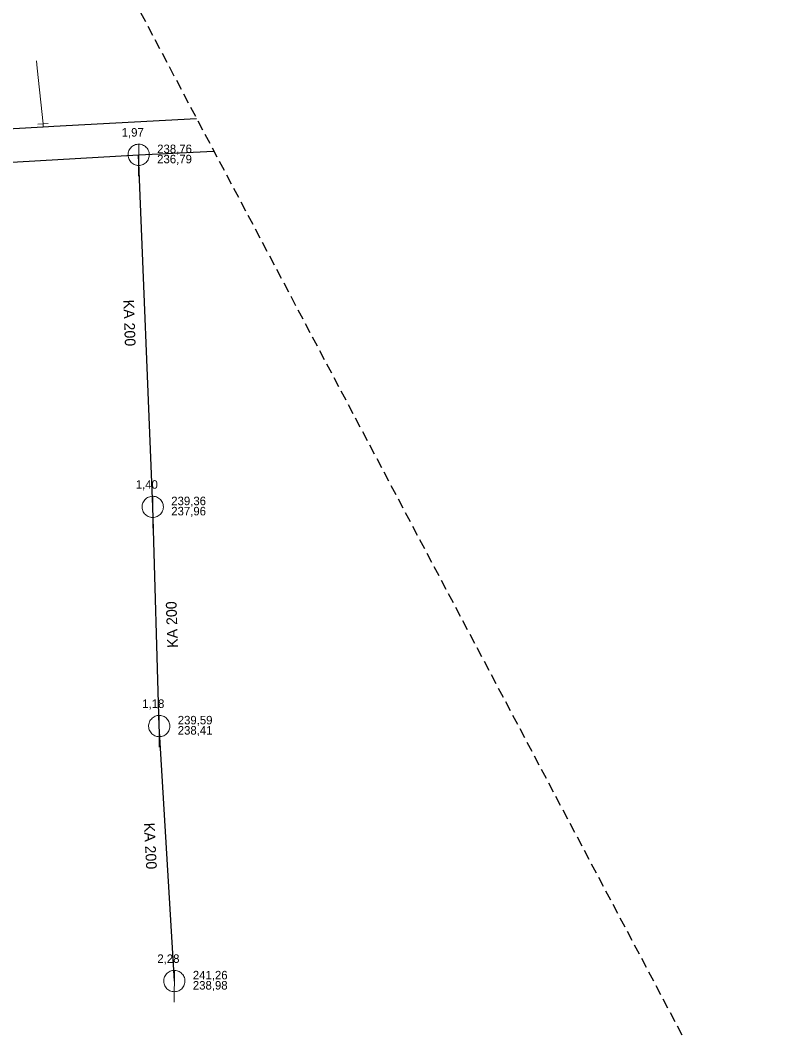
# Model space of a CAD drawing. Extents: x -777996 to -777727, y -976581 to -976199.
# Drawn here: x -777798.1 to -777726.8, y -976473.6 to -976378.6 of the extents above; entities that cross this region are included whole.
import ezdxf

# ---------------------------------------------------------------- set-up
doc = ezdxf.new("R2010")
doc.units = 0
doc.header["$LTSCALE"] = 0.32
doc.linetypes.add('MEDIUM_DASHED', pattern=[4.5, 3, -1.5])
for name, color, linetype, lineweight in [('1', 7, 'MEDIUM_DASHED', 25), ('13', 7, 'Continuous', 13), ('14', 7, 'Continuous', 25), ('17', 7, 'Continuous', 25), ('22', 7, 'Continuous', 13), ('34', 7, 'Continuous', 13)]:
    doc.layers.add(name, color=color, linetype=linetype, lineweight=lineweight)

msp = doc.modelspace()

# ---------------------------------------------------------------- linework, layer by layer
at = {"layer": '1'}
msp.add_lwpolyline([(-777995.417, -976203.033), (-777848.18, -976198.846), (-777864.927, -976230.247), (-777726.762, -976491.225), (-777789.565, -976581.242), (-777941.686, -976558.215), (-777989.136, -976405.396)], close=True, dxfattribs=at)
at = {"layer": '13'}
msp.add_lwpolyline([(-777795.959, -976388.351), (-777796.511, -976383.099), (-777796.57, -976382.41)], dxfattribs=at)
at = {"layer": '14', "lineweight": 13}
msp.add_line((-777795.936, -976388.625), (-777795.959, -976388.351), dxfattribs=at)
at = {"layer": '14'}
for p, q in [((-777785.625, -976424.436), (-777786.952, -976391.269)), ((-777785.013, -976445.085), (-777785.625, -976424.436)), ((-777783.592, -976469.103), (-777785.013, -976445.085))]:
    msp.add_line(p, q, dxfattribs=at)
msp.add_lwpolyline([(-777815.219, -976392.916), (-777786.952, -976391.269), (-777779.87, -976390.911)], dxfattribs=at)
at = {"layer": '17'}
msp.add_lwpolyline([(-777835.751, -976390.694), (-777818.616, -976389.892), (-777817.883, -976389.866), (-777816.903, -976389.831), (-777811.028, -976389.493), (-777795.936, -976388.625), (-777794.949, -976388.572), (-777781.49, -976387.851)], dxfattribs=at)
at = {"layer": '22'}
for p, q in [((-777786.952, -976393.269), (-777786.951, -976390.269)), ((-777785.625, -976426.436), (-777785.624, -976423.436)), ((-777785.014, -976447.085), (-777785.013, -976444.085)), ((-777783.593, -976471.103), (-777783.592, -976468.103))]:
    msp.add_line(p, q, dxfattribs=at)
for points in [[(-777785.952, -976391.269), (-777785.957, -976391.16), (-777785.975, -976391.052), (-777786.005, -976390.946), (-777786.045, -976390.845), (-777786.097, -976390.748), (-777786.159, -976390.658), (-777786.231, -976390.575), (-777786.311, -976390.501), (-777786.399, -976390.435), (-777786.493, -976390.38), (-777786.593, -976390.335), (-777786.698, -976390.302), (-777786.805, -976390.28), (-777786.914, -976390.27), (-777787.024, -976390.272), (-777787.132, -976390.286), (-777787.239, -976390.311), (-777787.342, -976390.348), (-777787.44, -976390.397), (-777787.532, -976390.455), (-777787.618, -976390.524), (-777787.695, -976390.601), (-777787.764, -976390.687), (-777787.823, -976390.779), (-777787.871, -976390.877), (-777787.908, -976390.98), (-777787.934, -976391.087), (-777787.948, -976391.195), (-777787.951, -976391.305), (-777787.941, -976391.414), (-777787.92, -976391.521), (-777787.886, -976391.625), (-777787.842, -976391.725), (-777787.787, -976391.82), (-777787.721, -976391.908), (-777787.647, -976391.988), (-777787.564, -976392.06), (-777787.474, -976392.122), (-777787.378, -976392.174), (-777787.276, -976392.215), (-777787.171, -976392.245), (-777787.063, -976392.263), (-777786.953, -976392.269), (-777786.844, -976392.263), (-777786.736, -976392.245), (-777786.631, -976392.216), (-777786.529, -976392.175), (-777786.432, -976392.123), (-777786.342, -976392.061), (-777786.259, -976391.99), (-777786.184, -976391.91), (-777786.119, -976391.822), (-777786.063, -976391.728), (-777786.019, -976391.628), (-777785.985, -976391.524), (-777785.963, -976391.416), (-777785.953, -976391.307)], [(-777784.625, -976424.436), (-777784.63, -976424.327), (-777784.648, -976424.219), (-777784.678, -976424.113), (-777784.718, -976424.012), (-777784.77, -976423.915), (-777784.832, -976423.825), (-777784.904, -976423.742), (-777784.984, -976423.668), (-777785.072, -976423.602), (-777785.166, -976423.547), (-777785.266, -976423.502), (-777785.371, -976423.469), (-777785.478, -976423.447), (-777785.587, -976423.437), (-777785.697, -976423.439), (-777785.805, -976423.453), (-777785.912, -976423.478), (-777786.015, -976423.515), (-777786.113, -976423.564), (-777786.205, -976423.622), (-777786.291, -976423.691), (-777786.368, -976423.768), (-777786.437, -976423.854), (-777786.496, -976423.946), (-777786.544, -976424.044), (-777786.581, -976424.147), (-777786.607, -976424.254), (-777786.621, -976424.362), (-777786.624, -976424.472), (-777786.614, -976424.581), (-777786.593, -976424.688), (-777786.559, -976424.792), (-777786.515, -976424.892), (-777786.46, -976424.987), (-777786.394, -976425.075), (-777786.32, -976425.155), (-777786.237, -976425.227), (-777786.147, -976425.289), (-777786.051, -976425.341), (-777785.949, -976425.382), (-777785.844, -976425.412), (-777785.736, -976425.43), (-777785.626, -976425.436), (-777785.517, -976425.43), (-777785.409, -976425.412), (-777785.304, -976425.383), (-777785.202, -976425.342), (-777785.105, -976425.29), (-777785.015, -976425.228), (-777784.932, -976425.157), (-777784.857, -976425.077), (-777784.792, -976424.989), (-777784.736, -976424.895), (-777784.692, -976424.795), (-777784.658, -976424.691), (-777784.636, -976424.583), (-777784.626, -976424.474)], [(-777784.014, -976445.085), (-777784.019, -976444.976), (-777784.037, -976444.868), (-777784.067, -976444.762), (-777784.107, -976444.661), (-777784.159, -976444.564), (-777784.221, -976444.474), (-777784.293, -976444.391), (-777784.373, -976444.317), (-777784.461, -976444.251), (-777784.555, -976444.196), (-777784.655, -976444.151), (-777784.76, -976444.118), (-777784.867, -976444.096), (-777784.976, -976444.086), (-777785.086, -976444.088), (-777785.194, -976444.102), (-777785.301, -976444.127), (-777785.404, -976444.164), (-777785.502, -976444.213), (-777785.594, -976444.271), (-777785.68, -976444.34), (-777785.757, -976444.417), (-777785.826, -976444.503), (-777785.885, -976444.595), (-777785.933, -976444.693), (-777785.97, -976444.796), (-777785.996, -976444.903), (-777786.01, -976445.011), (-777786.013, -976445.121), (-777786.003, -976445.23), (-777785.982, -976445.337), (-777785.948, -976445.441), (-777785.904, -976445.541), (-777785.849, -976445.636), (-777785.783, -976445.724), (-777785.709, -976445.804), (-777785.626, -976445.876), (-777785.536, -976445.938), (-777785.44, -976445.99), (-777785.338, -976446.031), (-777785.233, -976446.061), (-777785.125, -976446.079), (-777785.015, -976446.085), (-777784.906, -976446.079), (-777784.798, -976446.061), (-777784.693, -976446.032), (-777784.591, -976445.991), (-777784.494, -976445.939), (-777784.404, -976445.877), (-777784.321, -976445.806), (-777784.246, -976445.726), (-777784.181, -976445.638), (-777784.125, -976445.544), (-777784.081, -976445.444), (-777784.047, -976445.34), (-777784.025, -976445.232), (-777784.015, -976445.123)], [(-777782.593, -976469.103), (-777782.598, -976468.994), (-777782.616, -976468.886), (-777782.646, -976468.78), (-777782.686, -976468.679), (-777782.738, -976468.582), (-777782.8, -976468.492), (-777782.872, -976468.409), (-777782.952, -976468.335), (-777783.04, -976468.269), (-777783.134, -976468.214), (-777783.234, -976468.169), (-777783.339, -976468.136), (-777783.446, -976468.114), (-777783.555, -976468.104), (-777783.665, -976468.106), (-777783.773, -976468.12), (-777783.88, -976468.145), (-777783.983, -976468.182), (-777784.081, -976468.231), (-777784.173, -976468.289), (-777784.259, -976468.358), (-777784.336, -976468.435), (-777784.405, -976468.521), (-777784.464, -976468.613), (-777784.512, -976468.711), (-777784.549, -976468.814), (-777784.575, -976468.921), (-777784.589, -976469.029), (-777784.592, -976469.139), (-777784.582, -976469.248), (-777784.561, -976469.355), (-777784.527, -976469.459), (-777784.483, -976469.559), (-777784.428, -976469.654), (-777784.362, -976469.742), (-777784.288, -976469.822), (-777784.205, -976469.894), (-777784.115, -976469.956), (-777784.019, -976470.008), (-777783.917, -976470.049), (-777783.812, -976470.079), (-777783.704, -976470.097), (-777783.594, -976470.103), (-777783.485, -976470.097), (-777783.377, -976470.079), (-777783.272, -976470.05), (-777783.17, -976470.009), (-777783.073, -976469.957), (-777782.983, -976469.895), (-777782.9, -976469.824), (-777782.825, -976469.744), (-777782.76, -976469.656), (-777782.704, -976469.562), (-777782.66, -976469.462), (-777782.626, -976469.358), (-777782.604, -976469.25), (-777782.594, -976469.141)]]:
    msp.add_lwpolyline(points, close=True, dxfattribs=at)
at = {"layer": '34'}
msp.add_line((-777795.46, -976388.308), (-777796.457, -976388.392), dxfattribs=at)

# ---------------------------------------------------------------- texts
at = {"layer": '1'}
for s, p in [('1,97', (-777788.551, -976389.557)), ('1,40', (-777787.225, -976422.724)), ('1,18', (-777786.614, -976443.373)), ('2,28', (-777785.193, -976467.391))]:
    msp.add_text(s, height=0.8, dxfattribs=at).set_placement(p)
for rotation, p in [(272, (-777788.391, -976404.933)), (92, (-777783.245, -976437.699)), (273, (-777786.462, -976454.215))]:
    msp.add_text('KA 200', height=1, rotation=rotation, dxfattribs=at).set_placement(p)
at = {"layer": '22'}
for s, p in [('238,76', (-777785.209, -976391.108)), ('236,79', (-777785.209, -976392.068)), ('239,36', (-777783.882, -976424.275)), ('237,96', (-777783.882, -976425.235)), ('239,59', (-777783.271, -976444.924)), ('238,41', (-777783.271, -976445.884)), ('241,26', (-777781.85, -976468.943)), ('238,98', (-777781.85, -976469.903))]:
    msp.add_text(s, height=0.8, dxfattribs=at).set_placement(p)

doc.saveas('drawing.dxf')
